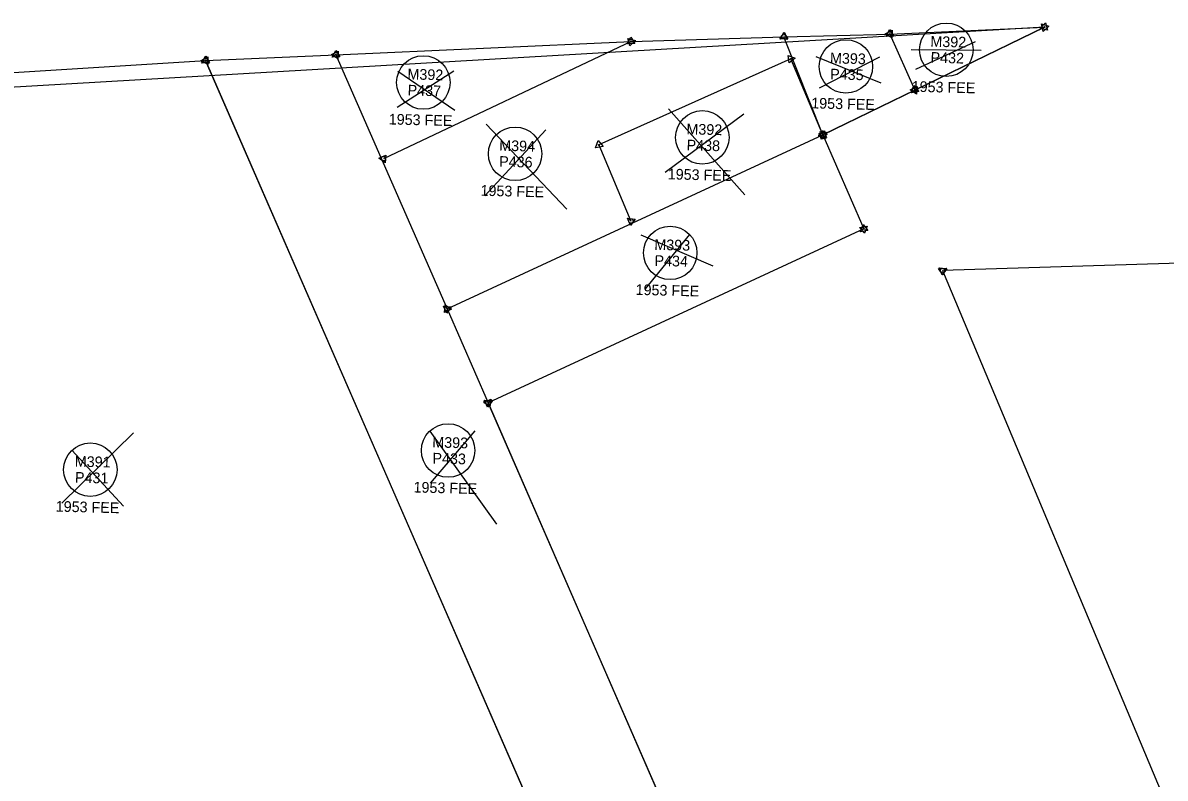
# Model space of a CAD drawing. Extents: x 325018 to 414989, y 1517547 to 1550415.
# Drawn here: x 359543 to 360104, y 1524943 to 1525314 of the extents above; entities that cross this region are included whole.
import ezdxf

# ---------------------------------------------------------------- set-up
doc = ezdxf.new("R2010")
doc.units = 0
for name, color, linetype in [('Level 56', 7, 'Continuous'), ('MHB', 7, 'Continuous'), ('MPL', 7, 'Continuous'), ('MRBL2', 7, 'Continuous'), ('MRBL3', 7, 'Continuous'), ('S_C', 7, 'Continuous')]:
    doc.layers.add(name, color=color, linetype=linetype)

msp = doc.modelspace()

# ---------------------------------------------------------------- linework, layer by layer
at = {"layer": 'Level 56'}
for centre in [(359996.45, 1525300.56), (359947.17, 1525292.38), (359739.82, 1525284.5), (359876.73, 1525257.55), (359784.85, 1525249.48), (359860.97, 1525200.83), (359751.99, 1525103.84), (359576.39, 1525094.43)]:
    msp.add_circle(centre, 13.12, dxfattribs=at)
at = {"layer": 'MHB'}
for p, q in [((359841.75, 1525304.59), (359916.72, 1525306.95)), ((359916.72, 1525306.95), (359968.71, 1525308.28)), ((359935.89, 1525258.76), (359916.72, 1525306.95)), ((359968.71, 1525308.28), (360044.63, 1525311.68)), ((359968.71, 1525308.28), (359980.95, 1525280.8)), ((360044.63, 1525311.68), (359980.95, 1525280.8)), ((359696.89, 1525298.1), (359841.75, 1525304.59)), ((359841.75, 1525304.59), (359720.2, 1525247.09)), ((358563.84, 1525229.33), (359632.96, 1525295.24)), ((359632.96, 1525295.24), (359696.89, 1525298.1)), ((359632.96, 1525295.24), (359814.81, 1524877.96)), ((359819.26, 1524868.15), (359632.96, 1525295.24)), ((359696.89, 1525298.1), (359751.53, 1525173.42)), ((359920.21, 1525296.09), (359826, 1525253.84)), ((359935.89, 1525258.76), (359920.21, 1525296.09)), ((359980.95, 1525280.8), (359935.89, 1525258.76)), ((359751.53, 1525173.42), (359935.89, 1525258.76)), ((359935.89, 1525258.76), (359955.98, 1525212.61)), ((359826, 1525253.84), (359841.69, 1525216.5)), ((359955.98, 1525212.61), (359771.61, 1525127.27)), ((359751.53, 1525173.42), (359771.61, 1525127.27)), ((359771.61, 1525127.27), (359883.19, 1524871.01))]:
    msp.add_line(p, q, dxfattribs=at)
for points in [[(360043.11, 1525313.24), (360046.74, 1525312.21)], [(360044.04, 1525309.58), (360043.11, 1525313.24)], [(360046.74, 1525312.21), (360044.04, 1525309.58)], [(359839.89, 1525303.44), (359841.68, 1525306.77)], [(359841.68, 1525306.77), (359843.67, 1525303.56)], [(359914.69, 1525306.14), (359917.03, 1525309.11)], [(359914.86, 1525305.81), (359916.66, 1525309.12)], [(359914.86, 1525305.8), (359916.65, 1525309.12)], [(359916.65, 1525309.12), (359918.64, 1525305.91)], [(359916.66, 1525309.12), (359918.63, 1525305.9)], [(359917.03, 1525309.11), (359918.43, 1525305.6)], [(359966.53, 1525308.36), (359969.87, 1525310.12)], [(359969.72, 1525306.34), (359966.53, 1525308.36)], [(359966.87, 1525307.1), (359968.61, 1525310.45)], [(359970.65, 1525307.27), (359966.87, 1525307.1)], [(359968.61, 1525310.45), (359970.65, 1525307.27)], [(359969.87, 1525310.12), (359969.72, 1525306.34)], [(359843.67, 1525303.56), (359839.89, 1525303.44)], [(359840.23, 1525306.16), (359843.86, 1525305.12)], [(359841.14, 1525302.49), (359840.23, 1525306.16)], [(359843.86, 1525305.12), (359841.14, 1525302.49)], [(359918.43, 1525305.6), (359914.69, 1525306.14)], [(359918.64, 1525305.91), (359914.86, 1525305.8)], [(359918.63, 1525305.9), (359914.86, 1525305.81)], [(359630.77, 1525295.29), (359634.09, 1525297.1)], [(359634, 1525293.32), (359630.77, 1525295.29)], [(359630.96, 1525294.37), (359633.2, 1525297.41)], [(359631.12, 1525294.06), (359632.86, 1525297.41)], [(359632.86, 1525297.41), (359634.89, 1525294.23)], [(359633.2, 1525297.41), (359634.71, 1525293.94)], [(359634.09, 1525297.1), (359634, 1525293.32)], [(359694.71, 1525298.17), (359698.04, 1525299.95)], [(359697.92, 1525296.18), (359694.71, 1525298.17)], [(359695.05, 1525296.92), (359696.8, 1525300.28)], [(359698.83, 1525297.09), (359695.05, 1525296.92)], [(359696.8, 1525300.28), (359698.83, 1525297.09)], [(359698.04, 1525299.95), (359697.92, 1525296.18)], [(359919.41, 1525294.07), (359918.85, 1525297.8)], [(359918.85, 1525297.8), (359922.36, 1525296.42)], [(359922.36, 1525296.42), (359919.41, 1525294.07)], [(359634.71, 1525293.94), (359630.96, 1525294.37)], [(359634.89, 1525294.23), (359631.12, 1525294.06)], [(359978.77, 1525280.96), (359982.17, 1525282.6)], [(359981.9, 1525278.84), (359978.77, 1525280.96)], [(359979.28, 1525279.39), (359980.57, 1525282.95)], [(359983, 1525280.05), (359979.28, 1525279.39)], [(359980.57, 1525282.95), (359983, 1525280.05)], [(359982.17, 1525282.6), (359981.9, 1525278.84)], [(359824.29, 1525252.48), (359825.68, 1525255.99)], [(359825.68, 1525255.99), (359828.03, 1525253.04)], [(359933.74, 1525258.41), (359936.67, 1525260.79)], [(359937.27, 1525257.06), (359933.74, 1525258.41)], [(359933.88, 1525257.91), (359936.17, 1525260.92)], [(359937.63, 1525257.44), (359933.88, 1525257.91)], [(359935.11, 1525256.73), (359934.52, 1525260.46)], [(359934.52, 1525260.46), (359938.05, 1525259.1)], [(359938.05, 1525259.1), (359935.11, 1525256.73)], [(359936.17, 1525260.92), (359937.63, 1525257.44)], [(359936.67, 1525260.79), (359937.27, 1525257.06)], [(359828.03, 1525253.04), (359824.29, 1525252.48)], [(359718.02, 1525247.27), (359721.44, 1525248.89)], [(359721.13, 1525245.13), (359718.02, 1525247.27)], [(359721.44, 1525248.89), (359721.13, 1525245.13)], [(359839.95, 1525217.82), (359843.7, 1525217.34)], [(359841.41, 1525214.33), (359839.95, 1525217.82)], [(359843.7, 1525217.34), (359841.41, 1525214.33)], [(359954.28, 1525211.23), (359955.63, 1525214.77)], [(359958.01, 1525211.84), (359954.28, 1525211.23)], [(359955.63, 1525214.77), (359958.01, 1525211.84)], [(359749.77, 1525174.72), (359753.52, 1525174.29)], [(359751.28, 1525171.25), (359749.77, 1525174.72)], [(359750.27, 1525171.64), (359750.61, 1525175.4)], [(359753.7, 1525173.22), (359750.27, 1525171.64)], [(359750.61, 1525175.4), (359753.7, 1525173.22)], [(359753.52, 1525174.29), (359751.28, 1525171.25)], [(359769.44, 1525127.47), (359772.87, 1525129.06)], [(359772.53, 1525125.3), (359769.44, 1525127.47)], [(359769.85, 1525128.57), (359773.61, 1525128.14)], [(359771.36, 1525125.11), (359769.85, 1525128.57)], [(359773.61, 1525128.14), (359771.36, 1525125.11)], [(359772.87, 1525129.06), (359772.53, 1525125.3)]]:
    msp.add_lwpolyline(points, dxfattribs=at)
for centre, radius in [((359916.72, 1525306.95), 1.09), ((359916.72, 1525306.95), 1.09), ((359916.72, 1525306.95), 1.09), ((359968.71, 1525308.28), 1.09), ((359968.71, 1525308.28), 0.227), ((360044.63, 1525311.68), 0.227), ((359841.75, 1525304.59), 1.09), ((359841.75, 1525304.59), 0.227), ((359632.96, 1525295.24), 1.09), ((359632.96, 1525295.24), 1.09), ((359632.96, 1525295.24), 0.227), ((359696.89, 1525298.1), 1.09), ((359696.89, 1525298.1), 0.227), ((359920.21, 1525296.09), 0.227), ((359980.95, 1525280.8), 1.09), ((359980.95, 1525280.8), 0.227), ((359935.89, 1525258.76), 1.09), ((359935.89, 1525258.76), 0.227), ((359935.89, 1525258.76), 0.227), ((359826, 1525253.84), 0.227), ((359720.2, 1525247.09), 1.09), ((359841.69, 1525216.5), 1.09), ((359955.98, 1525212.61), 0.227), ((359751.53, 1525173.42), 1.09), ((359751.53, 1525173.42), 0.227), ((359771.61, 1525127.27), 1.09), ((359771.61, 1525127.27), 0.227)]:
    msp.add_circle(centre, radius, dxfattribs=at)
at = {"layer": 'MPL'}
for p, q in [((360044.63, 1525311.68), (358028.86, 1525194.35)), ((359935.89, 1525258.76), (360044.63, 1525311.68)), ((359861.97, 1524920.11), (359771.61, 1525127.27))]:
    msp.add_line(p, q, dxfattribs=at)
for points in [[(360042.53, 1525311.13), (360045.21, 1525313.78)], [(360045.21, 1525313.78), (360046.17, 1525310.13)], [(360046.17, 1525310.13), (360042.53, 1525311.13)], [(359933.85, 1525259.51), (359937.57, 1525260.15)], [(359936.26, 1525256.61), (359933.85, 1525259.51)], [(359937.57, 1525260.15), (359936.26, 1525256.61)], [(359953.94, 1525213.38), (359957.67, 1525213.99)], [(359956.33, 1525210.46), (359953.94, 1525213.38)], [(359957.67, 1525213.99), (359956.33, 1525210.46)], [(359769.58, 1525128.05), (359773.31, 1525128.65)], [(359771.96, 1525125.12), (359769.58, 1525128.05)], [(359773.31, 1525128.65), (359771.96, 1525125.12)]]:
    msp.add_lwpolyline(points, dxfattribs=at)
for centre in [(360044.63, 1525311.68), (359935.89, 1525258.76), (359955.98, 1525212.61), (359771.61, 1525127.27)]:
    msp.add_circle(centre, 0.227, dxfattribs=at)
at = {"layer": 'MRBL2'}
msp.add_line((360490.4, 1525207.39), (359994.63, 1525192.19), dxfattribs=at)
for points in [[(359992.71, 1525193.23), (359996.49, 1525193.34)], [(359994.7, 1525190.01), (359992.71, 1525193.23)], [(359996.49, 1525193.34), (359994.7, 1525190.01)]]:
    msp.add_lwpolyline(points, dxfattribs=at)
msp.add_circle((359994.63, 1525192.19), 1.09, dxfattribs=at)
at = {"layer": 'MRBL3'}
msp.add_line((359994.63, 1525192.19), (360153.1, 1524814.1), dxfattribs=at)
for points in [[(359992.89, 1525193.51), (359996.64, 1525193.03)], [(359994.35, 1525190.02), (359992.89, 1525193.51)], [(359996.64, 1525193.03), (359994.35, 1525190.02)]]:
    msp.add_lwpolyline(points, dxfattribs=at)
msp.add_circle((359994.63, 1525192.19), 1.09, dxfattribs=at)
at = {"layer": 'S_C'}
for p, q in [((360010.64, 1525304.52), (359981.34, 1525290.8)), ((359932.4, 1525297.28), (359964.27, 1525284.29)), ((359963.73, 1525296.97), (359934.08, 1525281.75)), ((359979.27, 1525300.66), (360013.6, 1525300.32)), ((359754.77, 1525290.12), (359726.93, 1525272.22)), ((359727.25, 1525290.02), (359755.23, 1525270.9)), ((359897.03, 1525269.01), (359858.46, 1525240.27)), ((359860.15, 1525271.51), (359897.52, 1525229.27)), ((359770.67, 1525264.08), (359810.27, 1525222.34)), ((359799.96, 1525261.26), (359770.04, 1525228.87)), ((359846.48, 1525209.65), (359881.83, 1525194.46)), ((359870.49, 1525209.87), (359848.72, 1525183.16)), ((359597.59, 1525112.53), (359562.41, 1525078.02)), ((359742.95, 1525113.36), (359775.7, 1525067.64)), ((359765.09, 1525113.46), (359743.17, 1525087.82)), ((359567.36, 1525103.95), (359592.66, 1525076.56))]:
    msp.add_line(p, q, dxfattribs=at)

# ---------------------------------------------------------------- texts
at = {"layer": 'Level 56'}
for s, p in [('M392', (359988.6, 1525302.08)), ('M393', (359939.34, 1525293.9)), ('P432', (359988.69, 1525294.2)), ('M392', (359731.98, 1525286.02)), ('P435', (359939.42, 1525286.02)), ('1953 FEE', (359979.42, 1525279.98)), ('P437', (359732.07, 1525278.14)), ('1953 FEE', (359930.14, 1525271.8)), ('1953 FEE', (359722.79, 1525263.92)), ('M392', (359868.89, 1525259.07)), ('M394', (359777.01, 1525251)), ('P438', (359868.98, 1525251.19)), ('P436', (359776.98, 1525243.13)), ('1953 FEE', (359859.71, 1525236.97)), ('1953 FEE', (359767.83, 1525228.91)), ('M393', (359853.14, 1525202.35)), ('P434', (359853.22, 1525194.47)), ('1953 FEE', (359843.94, 1525180.25)), ('M393', (359744.16, 1525105.35)), ('M391', (359568.73, 1525095.94)), ('P433', (359744.25, 1525097.48)), ('P431', (359568.82, 1525088.06)), ('1953 FEE', (359734.96, 1525083.26)), ('1953 FEE', (359559.37, 1525073.85))]:
    msp.add_text(s, height=5.249, rotation=358.5141, dxfattribs=at).set_placement(p)

doc.saveas('drawing.dxf')
